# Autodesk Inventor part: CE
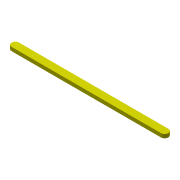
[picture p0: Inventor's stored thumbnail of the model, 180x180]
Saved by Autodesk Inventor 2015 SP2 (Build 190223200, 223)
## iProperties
Created: 2019-08
Part Number: CE
Material: 一般
Document SubType Name: Modeling
Designer: Kuan_Lun Hsu
Density: 1 g/cm^3
Appearance: Smooth - Yellow
Mass: 0.43927 g
Surface Area: 6.30686 cm^2
Volume: 0.43927 cm^3
Author: Kuan_Lun Hsu
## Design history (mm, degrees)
sketch "草圖1"
  geometry: L1 (0, 0)-(40, 0); L2 (0, -2.5)-(40, -2.5); L3 (40, 2.5)-(0, 2.5); A1 r 2.5 centre (0, 0) between (0, 2.5) and (0, -2.5); A2 r 2.5 centre (40, 0) between (40, -2.5) and (40, 2.5); 1 further point
  constraints: 8 end point, 4 point on circle, 4 tangent, 2 centre point, 1 horizontal, 1 midpoint, 1 parallel
  dimensions: "d0" = 40 distance of L1.start L1.end (= CE_); "d1" = 5 distance between parallel lines of L2 L3 (= w_)
extrude "擠出1" new body sketch "草圖1" distance "d2" = 2 (= t_); taper "d3" = 0 deg
node "實體1"
other parameters: "CE_" = 40 [user parameter; used in 1 equation term], "w_" = 5 [user parameter; used in 1 equation term], "t_" = 2 [user parameter; used in 1 equation term]
